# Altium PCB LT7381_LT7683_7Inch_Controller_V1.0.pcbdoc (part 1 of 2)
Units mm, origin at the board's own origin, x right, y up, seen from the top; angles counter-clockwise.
Board outline 88.99 x 77.25 mm, 2 copper layers (Top Layer, Bottom Layer); 119 components, 133 nets, 535 pads, 215 vias.
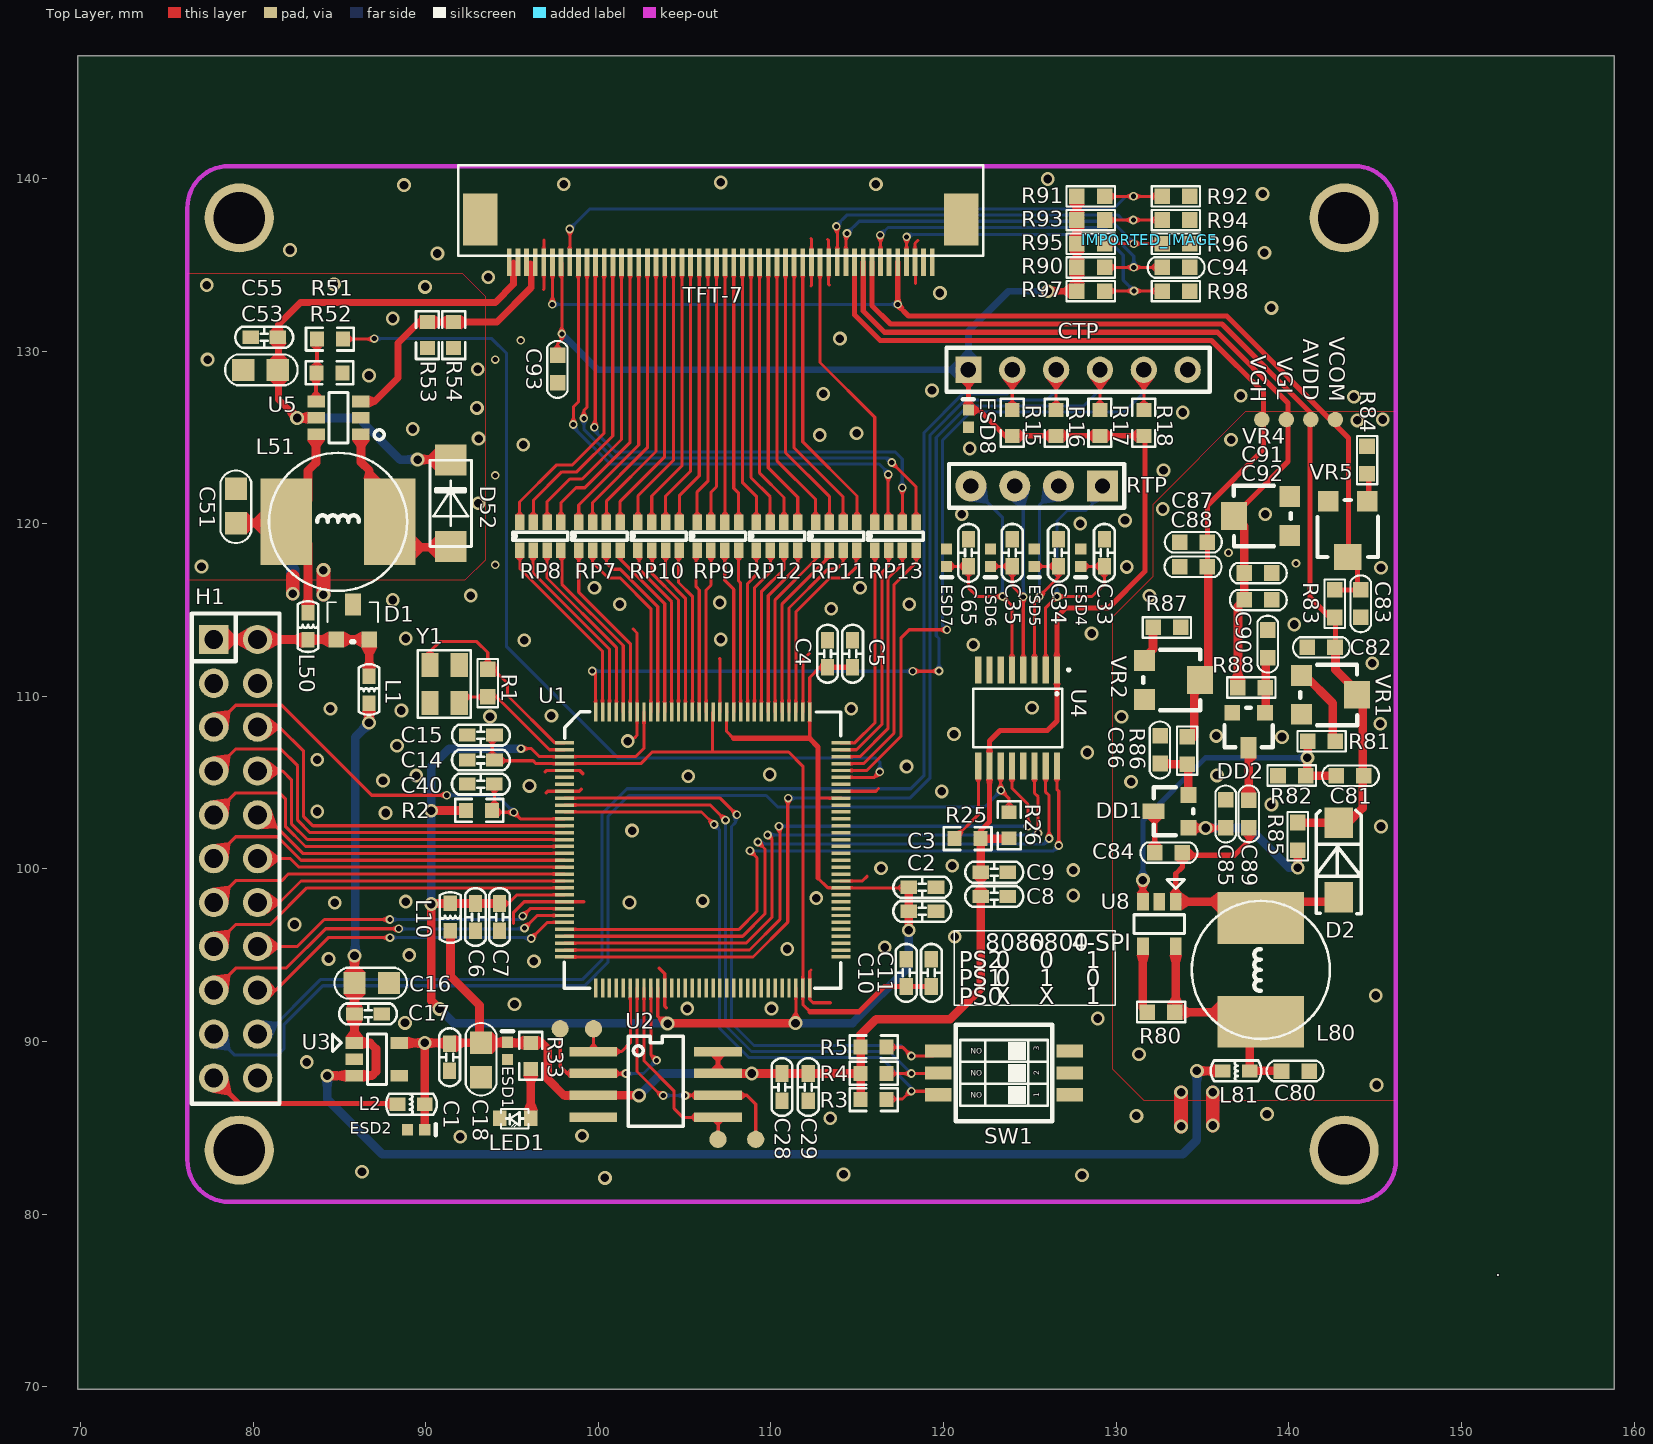
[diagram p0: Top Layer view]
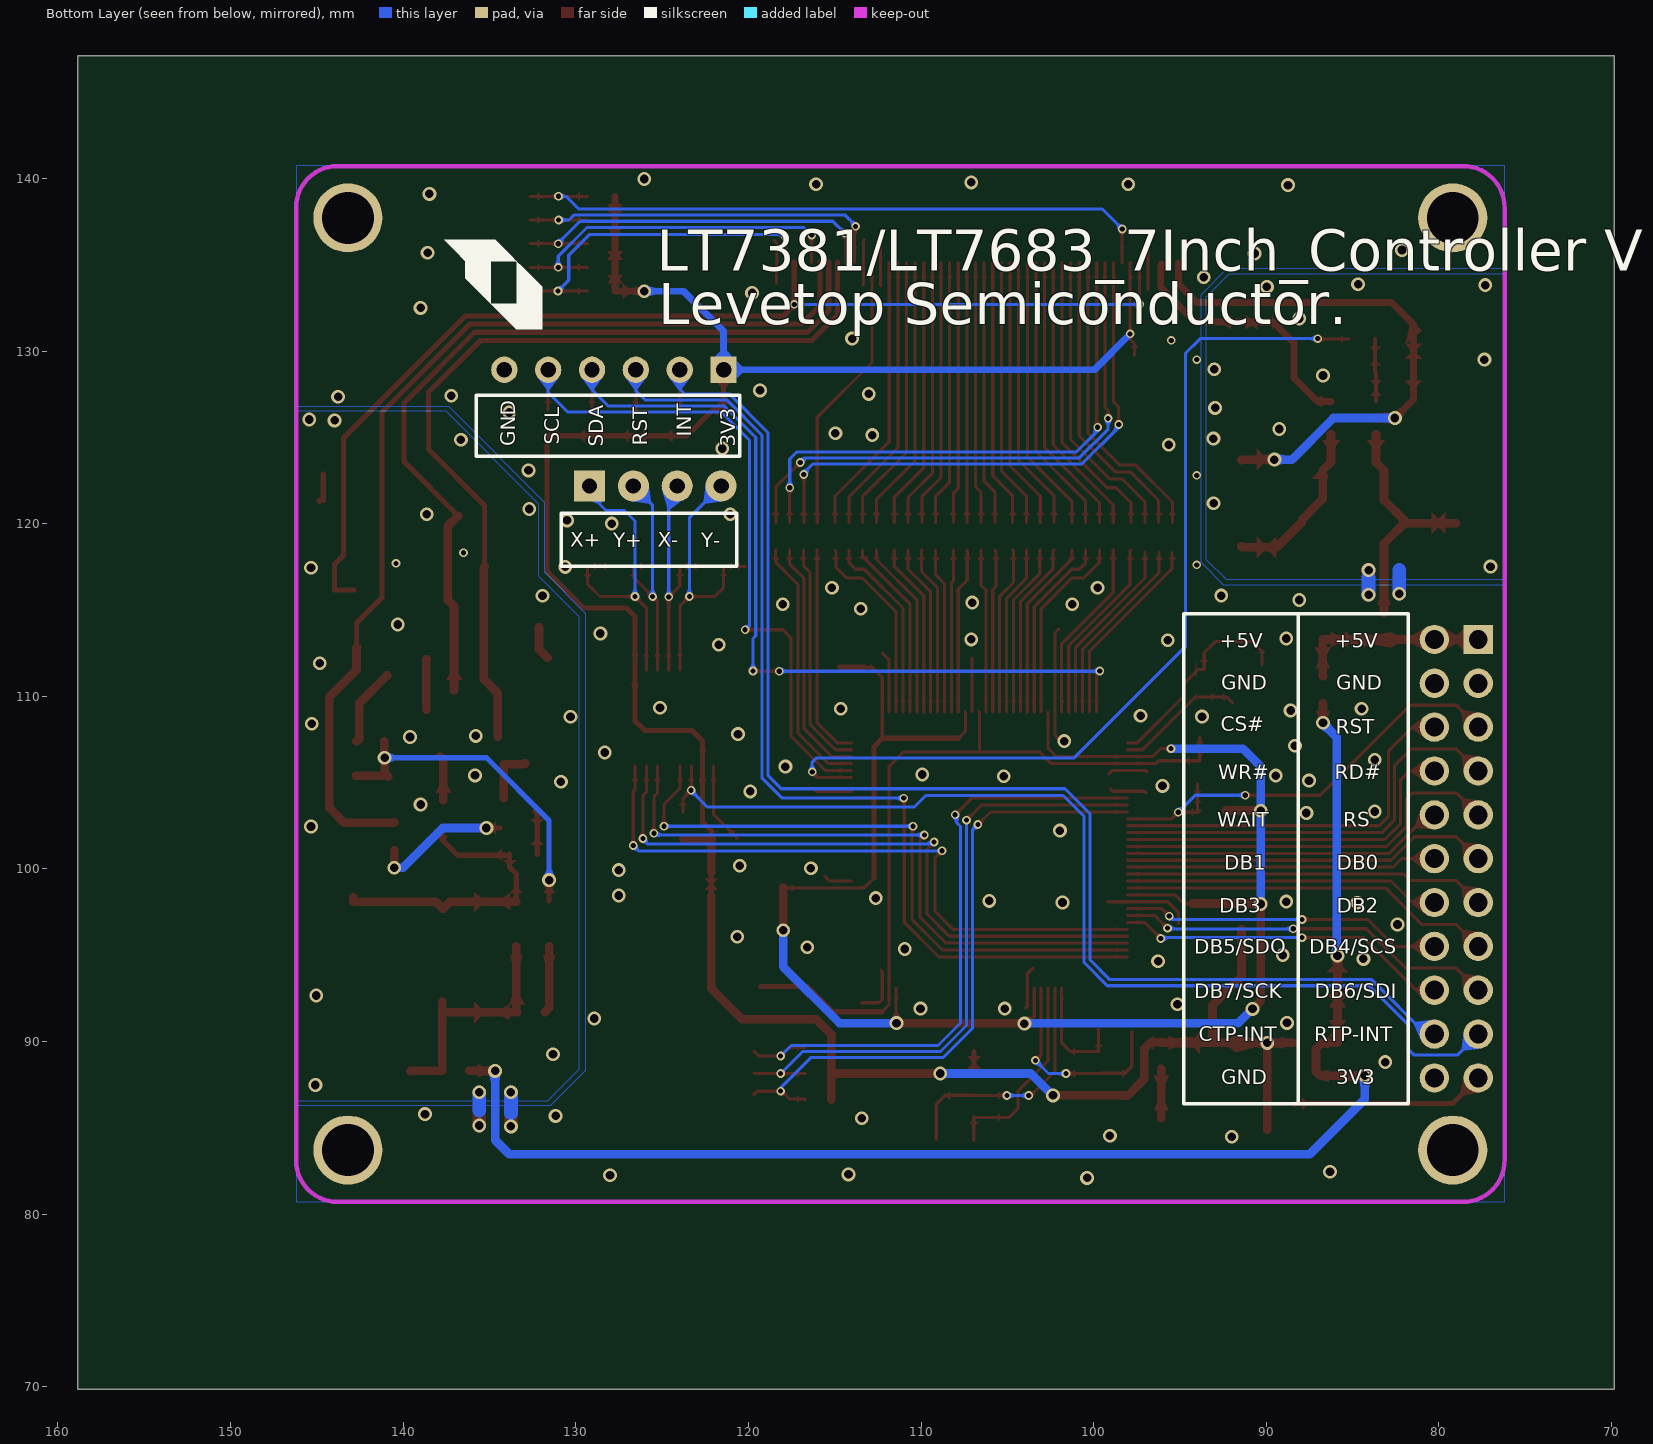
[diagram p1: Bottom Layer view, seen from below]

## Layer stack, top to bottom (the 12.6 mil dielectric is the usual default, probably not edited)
Top Layer: signal copper (thickness not stored)
Dielectric: dielectric 0.32, FR-4, Dk 4.8
Bottom Layer: signal copper (thickness not stored)

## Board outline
158.844,69.85 69.85,69.85 69.85,147.102 158.844,147.102

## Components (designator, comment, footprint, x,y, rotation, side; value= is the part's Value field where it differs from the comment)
C1 "1uF" C0603 91.389,89.878 r270 top
C2 "1uF" C0603 117.983,97.548 r0 top
C3 "0.1uf" C0603 117.983,98.945 r0 top
C4 "1uF" C0603 113.277,111.684 r90 top
C5 "0.1uf" C0603 114.731,111.684 r90 top
C6 "1uF" C0603 92.884,98 r270 top
C7 "0.1uf" C0603 94.281,98 r270 top
C8 "1uF" C0603 122.151,98.413 r0 top
C9 "0.1uf" C0603 122.151,99.81 r0 top
C10 "1uF" C0603 117.834,93.198 r90 top
C11 "0.1uf" C0603 119.288,93.198 r90 top
C14 "1uF" C0603 93.98,106.311 r180 top
C15 "0.1uf" C0603 93.981,107.752 r180 top
C16 "10uF" C0805 85.87,93.397 r0 top
C17 "1uF" C0603 85.878,91.608 r0 top
C18 "10uF" C0805 93.218,89.929 r270 top
C28 "1uF" C0603 110.638,88.15 r270 top
C29 "0.1uf" C0603 112.162,88.15 r270 top
C33 "20pF" C0603 129.314,117.53 r90 top
C34 "20pF" C0603 126.647,117.53 r90 top
C35 "20pF" C0603 123.98,117.53 r90 top
C40 "1uF" C0603 93.978,104.913 r180 top
C51 "22uF/50V" C0805_1 78.994,120.027 r90 top
C53 "22uF/50V" C0805_1 81.433,128.901 r180 top
C55 "0.1uF/50V" C0603 81.432,130.797 r180 top
C65 "20pF" C0603 121.44,117.53 r90 top
C80 "10uF" C0603_1 141.173,88.29 r180 top
C81 "100pF" C0603_1 142.748,105.41 r0 top
C82 "10uF/25V" C0603_1 141.072,112.84 r0 top
C83 "1uF" C0603_1 144.17,116.18 r270 top
C84 "1uF" C0603_1 132.232,100.953 r0 top
C85 "0.1uF" C0603_1 136.347,104.001 r270 top
C86 "0.1uF" C0603_1 132.537,107.709 r270 top
C87 "0.1uF" C0603_1 135.28,118.923 r180 top
C88 "1uF" C0603_1 135.267,117.501 r180 top
C89 "1uF" C0603_1 137.668,102.375 r90 top
C90 "0.1uF" C0603_1 138.786,113.843 r270 top
C91 "0.1uF" C0603_1 137.414,117.145 r0 top
C92 "1uF" C0603_1 137.414,115.583 r0 top
C93 "1uF" C0603_1 97.638,129.756 r270 top
C94 "0.1uF" C0603_1 132.652,134.849 r0 top
CTP "HDR_6P" SIP-6P 121.437,128.917 r0 top
D1 "MMBZ5V6A" SOT-23 84.836,113.296 r0 top
D2 "B340A" SOD-323 142.9,98.349 r0 top
D52 "B340A" DO-214 91.44,121.17 r90 top
DD1 "DAN217U" SOT23 133.198,103.34 r90 top
DD2 "DAN217U_SOT-23" SOT23 137.668,108.065 r180 top
ESD1 "PESD0402MS05" ESD0402 94.742,88.964 r90 top
ESD2 "PESD0402MS05" ESD0402 88.951,84.9 r0 top
ESD4 "PESD0402MS05" ESD0402 127.94,118.528 r270 top
ESD5 "PESD0402MS05" ESD0402 125.25,118.528 r270 top
ESD6 "PESD0402MS05" ESD0402 122.71,118.528 r270 top
ESD7 "PESD0402MS05" ESD0402 120.17,118.528 r270 top
ESD8 "PESD0402MS05" ESD0402 121.437,125.59 r90 top
H1 "CS-1106-2*11B" HDR-TH_22P-P2.54-V-M-R2-C11-S2.54 78.994,100.596 r270 top
IMPORTED_IMAGE "IMPORTED_IMAGE" IMPORTED_IMAGE 131.928,136.443 r0 top
L1 "BEAD 0603 600R&amp;100MHZ" L0603 86.716,110.376 r270 top
L2 "BEAD 0603 600R&amp;100MHZ" L0603 89.154,86.373 r180 top
L10 "BEAD 0603 600R&amp;100MHZ" L0603 91.423,97.215 r90 top
L50 "BEAD 0603 600R&amp;100MHZ" L0603 83.185,114.058 r90 top
L51 "10uH 1A" IND8A 84.916,120.105 r0 top
L80 "10uH/1A" IND8A 138.379,94.146 r90 top
L81 "BEAD 0603 600R&amp;100MHZ" L0603 136.957,88.304 r0 top
LED1 "LED_1" 0603LED 96.085,85.572 r180 top
R1 "1M" R0603_1 93.597,111.565 r270 top
R2 "120R" R0603 93.1,103.39 r180 top
R3 "10K" R0603 115.951,86.645 r180 top
R4 "10K" R0603 115.951,88.164 r180 top
R5 "10K" R0603 115.951,89.693 r180 top
R15 "10K" R0603 123.977,125.844 r90 top
R16 "10K" R0603 126.517,125.836 r90 top
R17 "10K" R0603 129.057,125.844 r90 top
R18 "10K" R0603 131.597,125.844 r90 top
R25 "0R" R0603 121.387,101.761 r0 top
R26 "10K" R0603 123.8,102.532 r90 top
R33 "4.7K" R0603 96.085,89.172 r90 top
R51 "100R" R0603 84.455,130.695 r180 top
R52 "10K" R0603 84.43,128.74 r0 top
R53 "12R" R0603 91.622,130.925 r270 top
R54 "12R" R0603 90.098,130.925 r270 top
R80 "10K" R0603_1 133.401,91.707 r180 top
R81 "100K" R0603_1 142.697,107.391 r180 top
R82 "18K" R0603_1 140.97,105.41 r180 top
R83 "150K" R0603_1 142.646,114.567 r90 top
R84 "100K" R0603_1 144.526,122.885 r90 top
R85 "0R" R0603_1 140.513,101.092 r90 top
R86 "2.2K" R0603_1 134.112,107.658 r270 top
R87 "100K" R0603_1 132.131,113.995 r0 top
R88 "3.3K" R0603_1 138.633,110.503 r180 top
R90 "10K" R0603_1 127.725,134.849 r0 top
R91 "10K" R0603_1 127.725,138.964 r0 top
R92 "NC" R0603_1 132.652,138.964 r0 top
R93 "10K" R0603_1 127.725,137.593 r0 top
R94 "NC" R0603_1 132.652,137.593 r0 top
R95 "NC" R0603_1 127.725,136.221 r0 top
R96 "10K" R0603_1 132.652,136.221 r0 top
R97 "NC" R0603_1 127.725,133.478 r0 top
R98 "10K" R0603_1 132.652,133.478 r0 top
RP7 "22R" 8R4R 100.076,119.265 r90 top
RP8 "22R" 8R4R 96.647,119.265 r90 top
RP9 "22R" 8R4R 106.934,119.265 r90 top
RP10 "22R" 8R4R 103.505,119.265 r90 top
RP11 "22R" 8R4R 113.792,119.265 r90 top
RP12 "22R" 8R4R 110.363,119.265 r90 top
RP13 "22R" 8R4R 117.221,119.265 r90 top
RTP "CON4" SIP-4P 129.203,122.186 r180 top
SW1 "DSHP03TSGET" SW-SMD_6P-L5.4-W5.4-P1.27-LS8.4 123.495,88.189 r90 top
TFT-7 "TFT_50" FPC50-0.5 94.844,135.141 r0 top
U1 "LT768-136" LQFP128L 106.045,101.104 r90 top
U2 "XT25F128B/W25Q128B" SOP-8A 100.457,89.42 r0 top
U3 "HP5013 3-2" SOT23-5 85.879,89.933 r270 top
U4 "TSC2046" TSSOP-16_L5.0-W4.4-P0.65-LS6.4-BL-1 124.289,108.754 r180 top
U5 "HP2302D" SOT23-6 83.646,127.09 r90 top
U8 "HP2301(FP6736)" SOT23-5 133.452,98.108 r180 top
VR1 "50KΩ" RES-ADJ-SMD_G32AT 142.342,110.084 r270 top
VR2 "50KΩ" RES-ADJ-SMD_G32AT 133.248,110.947 r270 top
VR4 "50KΩ" RES-ADJ-SMD_G32AT 138.43,120.447 r90 top
VR5 "50KΩ" RES-ADJ-SMD_G32AT 143.408,119.685 r180 top
Y1 "10M" M3225_1 91.95,109.615 r90 top

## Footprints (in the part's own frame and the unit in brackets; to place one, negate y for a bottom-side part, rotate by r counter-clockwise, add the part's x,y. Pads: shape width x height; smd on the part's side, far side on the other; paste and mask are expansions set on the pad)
8R4R [mm]
  rect 0.9x0.55 smd mask+0.102: 1(-0.79,1.209) 2(-0.79,0.409) 3(-0.79,-0.391) 4(-0.79,-1.191) 5(0.81,-1.191) 6(0.81,-0.391) 7(0.81,0.409) 8(0.81,1.209)
  silkscreen extent -0.22,-1.59 0.24,1.61
0603LED [mm]
  rect 0.8x0.9 smd mask+0.102: 1(0,0) 2(1.8,0)
  silkscreen extent 0.13,-0.53 1.73,0.6
C0603 [mil]
  rect 38x30 smd mask+4: 1(-0.09,-0.02) 2(61.91,-0.02)
  silkscreen extent -35,-24 97,24
C0603_1 [mm]
  rect 0.9x0.9 smd mask+0.102: 1(0,0) 2(1.6,0)
  silkscreen extent -0.83,-0.6 2.47,0.58
C0805 [mm]
  rect 1.3x1.27 smd mask+0.102: 1(0.005,-0.011) 2(2.005,-0.011)
  silkscreen extent -1.15,-0.9 3.05,0.88
C0805_1 [mm]
  rect 1.3x1.27 smd mask+0.102: 1(0.005,-0.011) 2(2.005,-0.011)
  silkscreen extent -1.15,-0.9 3.05,0.88
DO-214 [mm]
  rect 1.8x1.8 smd mask+0.102: 1(-2.488,-0.011) 2(2.512,-0.011)
  silkscreen extent -2.49,-1.21 2.51,1.19
ESD0402 [mm]
  rect 0.65x0.65 smd mask+0.102: 1(1,0) 2(0,0)
  silkscreen extent 1.63,-0.32 1.63,0.33
FPC50-0.5 [mm]
  rect 0.28x1.6 smd mask+0.102: 1(0,0) 2(0.5,0) 3(1,0) 4(1.5,0) 5(2,0) 6(2.5,0) 7(3,0) 8(3.5,0) 9(4,0) 10(4.5,0) 11(5,0) 12(5.5,0) 13(6,0) 14(6.5,0) 15(7,0) 16(7.5,0) 17(8,0) 18(8.5,0) 19(9,0) 20(9.5,0) 21(10,0) 22(10.5,0) 23(11,0) 24(11.5,0) 25(12,0) 26(12.5,0) 27(13,0) 28(13.5,0) 29(14,0) 30(14.5,0) 31(15,0) 32(15.5,0) 33(16,0) 34(16.5,0) 35(17,0) 36(17.5,0) 37(18,0) 38(18.5,0) 39(19,0) 40(19.5,0) 41(20,0) 42(20.5,0) 43(21,0) 44(21.5,0) 45(22,0) 46(22.5,0) 47(23,0) 48(23.5,0) 49(24,0) 50(24.5,0)
  rect 2x3 smd mask+0.102: 51(-1.69,2.475) 52(26.19,2.475)
  silkscreen extent -2.95,0.38 27.45,5.61
HDR-TH_22P-P2.54-V-M-R2-C11-S2.54 [mm]
  rect 1.7x1.7 hole 1.1 paste+0 mask+0.051: 1(-12.7,-1.27)
  round 1.7 hole 1.1 paste+0 mask+0.051: 2(-12.7,1.27) 3(-10.16,-1.27) 4(-10.16,1.27) 5(-7.62,-1.27) 6(-7.62,1.27) 7(-5.08,-1.27) 8(-5.08,1.27) 9(-2.54,-1.27) 10(-2.54,1.27) 11(0,-1.27) 12(0,1.27) 13(2.54,-1.27) 14(2.54,1.27) 15(5.08,-1.27) 16(5.08,1.27) 17(7.62,-1.27) 18(7.62,1.27) 19(10.16,-1.27) 20(10.16,1.27) 21(12.7,-1.27) 22(12.7,1.27)
  silkscreen extent -14.2,-2.54 14.2,2.54
IMPORTED_IMAGE [mm]
IND8A [mm]
  rect 3x5 smd mask+0.102: 1(-2.992,0.003) 2(3.008,0.003)
  silkscreen extent -3.99,-4 4.01,4
L0603 [mil]
  rect 35.43x30 smd mask+4: 1(-31,0) 2(31,0)
  silkscreen extent -59,-24 57,24
LQFP128L [mm]
  rect 0.2x1.1 smd paste+0 mask+0.102: 1(6.2,8) 2(5.8,8) 3(5.4,8) 4(5,8) 5(4.6,8) 6(4.2,8) 7(3.8,8) 8(3.4,8) 9(3,8) 10(2.6,8) 11(2.2,8) 12(1.8,8) 13(1.4,8) 14(1,8) 15(0.6,8) 16(0.2,8) 17(-0.2,8) 18(-0.6,8) 19(-1,8) 20(-1.4,8) 21(-1.8,8) 22(-2.2,8) 23(-2.6,8) 24(-3,8) 25(-3.4,8) 26(-3.8,8) 27(-4.2,8) 28(-4.6,8) 29(-5,8) 30(-5.4,8) 31(-5.8,8) 32(-6.2,8) 65(-6.2,-8) 66(-5.8,-8) 67(-5.4,-8) 68(-5,-8) 69(-4.6,-8) 70(-4.2,-8) 71(-3.8,-8) 72(-3.4,-8) 73(-3,-8) 74(-2.6,-8) 75(-2.2,-8) 76(-1.8,-8) 77(-1.4,-8) 78(-1,-8) 79(-0.6,-8) 80(-0.2,-8) 81(0.2,-8) 82(0.6,-8) 83(1,-8) 84(1.4,-8) 85(1.8,-8) 86(2.2,-8) 87(2.6,-8) 88(3,-8) 89(3.4,-8) 90(3.8,-8) 91(4.2,-8) 92(4.6,-8) 93(5,-8) 94(5.4,-8) 95(5.8,-8) 96(6.2,-8)
  rect 1.1x0.2 smd paste+0 mask+0.102: 33(-8,6.2) 34(-8,5.8) 35(-8,5.4) 36(-8,5) 37(-8,4.6) 38(-8,4.2) 39(-8,3.8) 40(-8,3.4) 41(-8,3) 42(-8,2.6) 43(-8,2.2) 44(-8,1.8) 45(-8,1.4) 46(-8,1) 47(-8,0.6) 48(-8,0.2) 49(-8,-0.2) 50(-8,-0.6) 51(-8,-1) 52(-8,-1.4) 53(-8,-1.8) 54(-8,-2.2) 55(-8,-2.6) 56(-8,-3) 57(-8,-3.4) 58(-8,-3.8) 59(-8,-4.2) 60(-8,-4.6) 61(-8,-5) 62(-8,-5.4) 63(-8,-5.8) 64(-8,-6.2) 97(8,-6.2) 98(8,-5.8) 99(8,-5.4) 100(8,-5) 101(8,-4.6) 102(8,-4.2) 103(8,-3.8) 104(8,-3.4) 105(8,-3) 106(8,-2.6) 107(8,-2.2) 108(8,-1.8) 109(8,-1.4) 110(8,-1) 111(8,-0.6) 112(8,-0.2) 113(8,0.2) 114(8,0.6) 115(8,1) 116(8,1.4) 117(8,1.8) 118(8,2.2) 119(8,2.6) 120(8,3) 121(8,3.4) 122(8,3.8) 123(8,4.2) 124(8,4.6) 125(8,5) 126(8,5.4) 127(8,5.8) 128(8,6.2)
  silkscreen extent -8,-8.01 8,8.01
M3225_1 [mm]
  rect 1.4x1 smd mask+0.102: 1(0,0) 2(2.2,0) 3(2.2,1.7) 4(0,1.7)
  silkscreen extent -0.85,-0.65 3.05,2.4
R0603 [mm]
  rect 0.806x0.864 smd paste-100 mask+0.051: 1(-0.753,0) 2(0.753,0)
  silkscreen extent -1.39,-0.66 1.39,0.66
R0603_1 [mm]
  rect 0.9x0.9 smd mask+0.102: 1(0,0) 2(1.6,0)
  silkscreen extent -0.6,-0.6 2.2,0.58
RES-ADJ-SMD_G32AT [mil]
  rect 47.2x47.2 smd paste+0 mask+2: 1(44.3,-63.5) 3(-44.3,-63.5)
  rect 63x59.1 smd paste+0 mask+2: 2(0,63.5)
  silkscreen extent -69,-66 69,64
SIP-4P [mm]
  rect 1.8x1.8 hole 0.889 mask+0.102: 1(0,0)
  round 1.8 hole 0.889 mask+0.102: 2(2.54,0) 3(5.08,0) 4(7.62,0)
  silkscreen extent -1.27,-1.27 8.89,1.27
SIP-6P [mil]
  rect 60x60 hole 35 mask+4: 1(0,0)
  round 60 hole 35 mask+4: 2(100,0) 3(200,0) 4(300,0) 5(400,0) 6(500,0)
  silkscreen extent -50,-50 550,50
SOD-323 [mil]
  rect 65x70 smd mask+4: 1(-0.42,0.31) 2(-0.42,170.31)
  silkscreen extent -51,-37 51,199
SOP-8A [mm]
  rect 2.778x0.55 smd mask+0.102: 1(-0.75,0.005) 2(-0.75,-1.265) 3(-0.75,-2.535) 4(-0.75,-3.805) 5(6.473,-3.805) 6(6.473,-2.535) 7(6.473,-1.265) 8(6.473,0.005)
  silkscreen extent 1.27,-4.31 4.45,0.89
SOT23 [mil]
  rect 36x36 smd paste+0 mask+4: 1(-37.5,-39) 2(37.5,-39)
  rect 36x50 smd paste+0 mask+4: 3(0,41)
  silkscreen extent -55,-50 55,40
SOT23-5 [mil]
  rect 27x40 smd mask+4: 1(0.28,-0.14) 2(37.68,-0.14) 3(75.08,-0.14) 4(75.08,102.22) 5(0.28,102.22)
  silkscreen extent -20,-50 95,73
SOT23-6 [mil]
  rect 27x40 smd mask+4: 1(-75.07,-102.5) 2(-37.67,-102.5) 3(-0.27,-102.5) 4(-0.27,-0.14) 5(-37.67,-0.14) 6(-75.07,-0.14)
  silkscreen extent -95,-155 20,-30
SOT-23 [mil]
  rect 36x36 smd mask+4: 1(-0.41,-0.04) 2(74.59,-0.04)
  rect 36x50 smd mask+4: 3(37.59,79.96)
  silkscreen extent -20,-5 95,85
SW-SMD_6P-L5.4-W5.4-P1.27-LS8.4 [mil]
  rect 30x60 smd paste+0 mask+2: 1(-50,-150) 2(0,-150) 3(50,-150) 4(50,150) 5(0,150) 6(-50,150)
  silkscreen extent -110,-110 110,110
TSSOP-16_L5.0-W4.4-P0.65-LS6.4-BL-1 [mm]
  rect 0.364x1.56 smd paste+0 mask+0.051: 1(-2.275,-2.78) 2(-1.625,-2.78) 3(-0.975,-2.78) 4(-0.325,-2.78) 5(0.325,-2.78) 6(0.975,-2.78) 7(1.625,-2.78) 8(2.275,-2.78) 9(2.275,2.78) 10(1.625,2.78) 11(0.975,2.78) 12(0.325,2.78) 13(-0.325,2.78) 14(-0.975,2.78) 15(-1.625,2.78) 16(-2.275,2.78)
  silkscreen extent -3.03,-2.85 2.58,1.7

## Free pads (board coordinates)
  round 4 hole 3 mask+0.102: 1(79.2,83.716) 2(143.2,83.716) 3(143.2,137.716) 4(79.2,137.716)
  round 1 smd mask+0.102: TP4(109.118,84.341) TP5(106.934,84.341) TP6(99.72,90.742) TP7(97.79,90.742)
  round 0.9 smd mask+0.102: TP7(142.697,126.035) TP8(141.275,126.035) TP10(139.852,126.035) TP11(138.43,126.035)

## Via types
v1: diameter 0.8, hole 0.5, Top Layer to Bottom Layer, 151 vias
v2: diameter 0.5, hole 0.3, Top Layer to Bottom Layer, 64 vias

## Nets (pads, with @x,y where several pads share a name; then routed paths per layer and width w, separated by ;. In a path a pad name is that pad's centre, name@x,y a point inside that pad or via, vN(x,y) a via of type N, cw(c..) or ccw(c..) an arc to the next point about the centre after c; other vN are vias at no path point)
$1N16243: R51.2 R52.1 U5.4 | length 3.6
  Top Layer w0.254: U5.4@83.65,127.083 83.65,128.756 83.702,128.807 R51.2@83.702,130.695
$1N16244: C51.1 L50.2 L51.1 U5.6 | length 14.5
  Top Layer w0.5: C51.1@79.005,120.032 81.848,120.032 L51.1@81.924,120.108 ; L50.2@83.185,114.845 83.185,118.847 L51.1@81.924,120.108 ; U5.6@83.65,125.183 83.65,123.54 83.185,123.075 83.185,121.369 L51.1@81.924,120.108
$1N16251: D52.1 L51.2 U5.1 | length 9.9
  Top Layer w0.5: U5.1@86.25,125.183 86.25,123.566 86.741,123.075 86.741,121.424 87.924,120.241 L51.2@87.924,120.108 89.402,118.63 91.399,118.63 D52.1@91.451,118.682
$1N48183: U4.13
$1N48192: R25.1 U4.9 | length 4.8
  Top Layer w0.18: R25.1@120.633,101.761 122.014,103.141 U4.9@122.014,105.974
$1N53057: LED1.1 R33.1 | length 2.8
  Top Layer w0.5: LED1.1@96.085,85.572 R33.1@96.085,88.419
$1N79041: C90.2 DD2.1 R88.1 | length 2.9
  Top Layer w0.5: C90.2@138.633,112.154 138.651,112.136 DD2.1@138.651,109.228
$1N79043: C85.2 DD1.1 R85.1 | length 8.8
  Top Layer w0.3: DD1.1@134.391,102.388 134.404,102.375 v1(135.179,102.375) 135.864,102.375 135.89,102.401
  Top Layer w0.5: v1(140.513,100.076) R85.1@140.513,101.092
  Bottom Layer w0.5: v1(135.179,102.375) 137.706,102.375 140.005,100.076 v1(140.513,100.076)
$1N79044: C86.2 DD1.2 R86.2 | length 3.2
  Top Layer w0.5: C86.2@132.944,106.109 132.994,106.058 134.163,106.058 DD1.2@134.163,104.115
$1N79046: C84.2 C89.1 D2.1 L80.2 U8.1 | length 18
  Top Layer w0.3: U8.1@133.445,98.112 133.445,99.727 133.832,100.114 133.832,100.851 133.883,100.8 136.855,100.8 137.719,101.664 137.719,102.375 C89.1@137.668,102.375
  Top Layer w0.5: U8.1@133.445,98.112 137.27,98.112 137.689,97.693 138.104,98.108 142.863,98.108 142.89,98.135 D2.1@142.89,98.357
$1N79048: C81.1 R81.2 R82.1 U8.3 | length 19.6
  Top Layer w0.3: U8.3@131.545,98.162 v1(131.545,99.355)
  Top Layer w0.5: R82.1@140.868,105.359 141.072,105.562 v1(141.072,106.439) 141.097,106.465 R81.2@141.097,107.391 ; R82.1@140.97,105.41 C81.1@142.748,105.41
  Bottom Layer w0.3: v1(131.545,99.355) 131.545,102.805 135.179,106.439 v1(141.072,106.439)
$1N79058: C80.2 L80.1 L81.2 R80.1 U8.5 | length 14
  Top Layer w0.3: R80.1@133.401,91.707 R80.1@133.445,91.751
  Top Layer w0.5: R80.1@133.401,91.707 133.415,91.693 137.689,91.693 L80.1@137.744,91.637 ; R80.1@133.445,91.751 U8.5@133.445,95.512 ; L80.1@137.744,92.298 L80.1@137.744,91.637 ; C80.2@139.573,88.29 139.56,88.304 L81.2@137.744,88.304 L80.1@137.744,91.637
$1N83513: C89.2 DD2.3 | length 2.6
  Top Layer w0.5: C89.2@137.668,103.975 137.668,106.312 DD2.3@137.871,106.515
$1N83514: C84.1 DD1.3 | length 2.5
  Top Layer w0.3: C84.1@132.232,100.851 132.232,103.213 DD1.3@132.359,103.34
$1N95806: R81.1 VR1.3 | length 4.5
  Top Layer w0.5: VR1.3@140.932,111.209 142.545,109.596 142.545,107.544 R81.1@142.697,107.391
$1N101796: R84.1 VR5.3 | length 1.6
  Top Layer w0.3: VR5.3@144.628,121.341 R84.1@144.628,122.885 ; VR5.3@144.838,121.298 VR5.3@144.882,121.341
$1N109903: R87.1 VR2.3 | length 2
  Top Layer w0.5: VR2.3@131.636,112.23 132.131,112.725 R87.1@132.131,113.995
+5V: C16.1 C17.1 L1.2 L81.1 U3.1 U3.3 | length 84.5
  Top Layer w0.5: v1(84.301,88.026) U3.3@85.875,88.026 86.879,88.026 87.125,88.272 87.125,89.572 86.771,89.926 U3.1@85.875,89.926 C17.1@85.875,91.607 C16.1@85.875,93.386 v1(85.875,94.972) ; v1(86.716,108.471) L1.2@86.716,109.589 ; v1(134.671,88.304) L81.1@136.169,88.304
  Bottom Layer w0.5: v1(84.301,88.026) 84.301,86.654 87.478,83.478 133.858,83.478 134.671,84.29 v1(134.671,88.304) ; v1(85.875,94.972) 85.925,95.022 85.925,107.63 86.716,108.42 v1(86.716,108.471)
B0: RP11.5 TFT-7.35 | length 16.4
  Top Layer w0.18: TFT-7.35@111.844,135.141 111.844,124.745 114.983,121.606 RP11.5@114.983,120.075
B1: RP11.6 TFT-7.34 | length 16.2
  Top Layer w0.18: TFT-7.34@111.344,135.141 111.344,124.382 114.183,121.542 RP11.6@114.183,120.075
B2: RP11.7 TFT-7.33 | length 16.1
  Top Layer w0.18: TFT-7.33@110.844,135.141 110.844,124.12 113.383,121.58 RP11.7@113.383,120.075
B3: RP11.8 TFT-7.32 | length 16
  Top Layer w0.18: TFT-7.32@110.344,135.141 110.344,123.654 112.583,121.415 RP11.8@112.583,120.075
B4: RP12.5 TFT-7.31 | length 15.8
  Top Layer w0.18: TFT-7.31@109.844,135.141 109.844,123.24 111.554,121.53 RP12.5@111.554,120.075
B5: RP12.6 TFT-7.30 | length 15.7
  Top Layer w0.18: TFT-7.30@109.344,135.141 109.344,122.927 110.754,121.517 RP12.6@110.754,120.075
B6: RP12.7 TFT-7.29 | length 15.5
  Top Layer w0.18: TFT-7.29@108.844,135.141 108.844,122.665 109.954,121.555 RP12.7@109.954,120.075
B7: RP12.8 TFT-7.28 | length 15.4
  Top Layer w0.18: TFT-7.28@108.344,135.141 108.344,122.403 109.154,121.593 RP12.8@109.154,120.075
CTP_INT: CTP.2 H1.20 R15.2 | length 79.2
  Top Layer w0.18: R15.2@123.977,126.597 CTP.2@123.977,128.917
  Bottom Layer w0.18: H1.20@80.264,90.436 80.747,90.436 83.897,93.587 99.06,93.587 100.203,94.73 100.203,103.187 101.664,104.648 118.097,104.648 118.872,105.423 118.872,125.286 121.107,127.521 123.698,127.521 123.977,127.801 CTP.2@123.977,128.917
CTP_RST: CTP.3 R16.2 U1.32 | length 61.4
  Top Layer w0.18: U1.32@98.045,94.904 108.957,94.904 110.975,96.922 110.975,104.079 v2(110.998,104.102) ; R16.2@126.517,126.589 CTP.3@126.517,128.917
  Bottom Layer w0.18: v2(110.998,104.102) 118.046,104.102 119.222,105.278 119.222,125.14 121.252,127.171 125.989,127.171 126.517,127.699 CTP.3@126.517,128.917
CTP_SCL: CTP.5 R18.2 U1.92 | length 40.4
  Top Layer w0.18: U1.92@114.045,105.704 115.557,105.704 117.525,107.672 117.525,113.373 118.008,113.856 v2(120.193,113.856) ; R18.2@131.597,126.597 CTP.5@131.597,128.917
  Bottom Layer w0.18: v2(120.193,113.856) 119.939,114.11 119.939,124.829 121.58,126.47 130.47,126.47 131.597,127.597 CTP.5@131.597,128.917
CTP_SDA: CTP.4 R17.2 U1.128 | length 50.3
  Top Layer w0.18: v2(99.644,111.467) 99.845,111.266 U1.128@99.845,109.104 ; v2(118.212,111.455) 119.722,111.455 v2(119.736,111.468) ; R17.2@129.057,126.597 CTP.4@129.057,128.917
  Bottom Layer w0.18: v2(99.644,111.467) 99.656,111.455 v2(118.212,111.455) ; v2(119.736,111.468) 119.736,113.348 119.573,113.511 119.573,124.995 121.398,126.82 128.128,126.82 129.057,127.75 CTP.4@129.057,128.917
DE: RP13.7 TFT-7.9 | length 31.9
  Top Layer w0.18: v2(98.552,125.743) 98.552,126.759 98.844,127.051 TFT-7.9@98.844,135.141 ; v2(116.789,122.848) 116.789,120.097 RP13.7@116.812,120.075
  Bottom Layer w0.18: v2(98.552,125.743) 98.552,125.594 100.683,123.462 116.263,123.462 116.789,122.936 v2(116.789,122.848)
DITH: R97.2 R98.1 TFT-7.47 | length 20.2
  Top Layer w0.18: TFT-7.47@117.844,135.141 117.856,135.154 v2(117.856,136.614) ; R97.2@129.325,133.478 v2(131.032,133.478) R98.1@132.652,133.478
  Bottom Layer w0.18: v2@117.856,136.716 117.958,136.716 118.001,136.759 129.193,136.759 130.404,135.548 130.404,134.106 v2(131.032,133.478)
FLASH_SPI_CS0: U1.37
FLASH_SPI_CS1: pad.TP6 U1.38 U2.1 | length 6.9
  Top Layer w0.18: pad.TP6@99.72,90.742 99.72,89.438 U2.1@99.707,89.425 101.351,89.425 101.854,89.928 101.854,93.095 U1.38@101.845,93.104
FLASH_SPI_SCLK: pad.TP4 U1.39 U2.6 | length 14.5
  Top Layer w0.18: U1.39@102.245,93.104 102.245,88.267 103.632,86.88 v2(103.759,86.88) ; v2(105.029,86.88) 105.034,86.885 U2.6@106.93,86.885
  Top Layer w0.2: U2.6@106.93,86.885 108.607,86.885 109.118,86.373 pad.TP4@109.118,84.341
  Bottom Layer w0.18: v2(103.759,86.88) v2(105.029,86.88)
FLASH_SPI_SI: pad.TP5 U1.40 U2.5 | length 11.8
  Top Layer w0.18: U1.40@102.645,93.104 102.645,88.883 104.394,87.134 104.394,86.118 104.897,85.615 U2.5@106.93,85.615
  Top Layer w0.2: U2.5@106.93,85.615 106.934,85.611 pad.TP5@106.934,84.29
FLASH_SPI_SO: pad.TP7@97.79,90.742 U1.41 U2.2 | length 12.4
  Top Layer w0.18: U2.2@99.707,88.155 99.712,88.15 v2(101.6,88.15) ; U1.41@103.045,93.104 103.045,89.245 v2(103.378,88.912)
  Top Layer w0.2: pad.TP7@97.79,90.539 97.79,88.558 98.193,88.155 U2.2@99.707,88.155
  Bottom Layer w0.18: v2(101.6,88.15) 102.616,88.15 v2(103.378,88.912)
G0: RP9.5 TFT-7.27 | length 15.2
  Top Layer w0.18: TFT-7.27@107.844,135.141 107.844,122.053 108.125,121.772 RP9.5@108.125,120.075
G1: RP9.6 TFT-7.26 | length 15.1
  Top Layer w0.18: RP9.6@107.325,120.075 107.34,120.09 107.34,121.265 107.344,121.268 TFT-7.26@107.344,135.141
G2: RP9.7 TFT-7.25 | length 15.2
  Top Layer w0.18: RP9.7@106.525,120.075 106.528,120.077 106.528,121.832 106.844,122.148 TFT-7.25@106.844,135.141
G3: RP9.8 TFT-7.24 | length 15.3
  Top Layer w0.18: RP9.8@105.725,120.075 105.725,121.842 106.344,122.46 TFT-7.24@106.344,135.141
G4: RP10.5 TFT-7.23 | length 15.5
  Top Layer w0.18: RP10.5@104.696,120.075 104.696,121.625 105.844,122.773 TFT-7.23@105.844,135.141
G5: RP10.6 TFT-7.22 | length 15.7
  Top Layer w0.18: RP10.6@103.896,120.075 103.896,121.587 105.344,123.035 TFT-7.22@105.344,135.141
G6: RP10.7 TFT-7.21 | length 15.8
  Top Layer w0.18: RP10.7@103.096,120.075 103.096,121.6 104.844,123.348 TFT-7.21@104.844,135.141
G7: RP10.8 TFT-7.20 | length 15.9
  Top Layer w0.18: RP10.8@102.296,120.075 102.296,121.613 104.344,123.661 TFT-7.20@104.344,135.141
GND: C1.2 C2.2 C3.2 C4.2 C5.2 C6.2 C7.2 C8.2 C9.2 C10.2 C11.2 C14.2 C15.2 C16.2 C17.2 C18.2 C28.2 C29.2 C33.2 C34.2 C35.2 C40.2 C51.2 C53.2 C55.2 C65.2 C80.1 C82.1 C83.2 C85.1 C86.1 C87.2 C88.2 C90.1 C91.2 C92.2 C93.2 C94.2 CTP.6 D1.3 DD2.2 ESD1.2 ESD2.2 ESD4.2 ESD5.2 ESD6.2 ESD7.2 ESD8.2 H1.3 H1.4 H1.22 LED1.2 pad.1 pad.2 pad.3 pad.4 R52.2 R53.2 R54.2 R82.2 R84.2 R87.2 R92.2 R94.2 R96.2 R98.2 SW1.1 SW1.2 SW1.3 TFT-7.5 TFT-7.36 TFT-7.38 TFT-7.48 TFT-7.51 TFT-7.52 U1.5 U1.6 U1.7 U1.8 U1.24 U1.43 U1.64 U1.76 U1.89 U1.98 U1.110 U1.122 U2.4 U3.2 U4.6 U5.2 U8.2 VR4.3 Y1.2 Y1.4 | length 53.7
  Top Layer w0.18: 95.098,96.838 95.098,97.498 95.703,98.104 U1.24@98.045,98.104 99.158,98.104 99.162,98.108 ; 96.825,133.566 96.844,133.585 TFT-7.5@96.844,135.141 96.844,136.443 ; 102.006,113.907 102.245,113.668 U1.122@102.245,109.104 102.245,107.745 102.108,107.608 ; 103.53,94.247 103.845,93.933 U1.43@103.845,93.104 103.845,92.053 103.937,91.961 ; 107.036,112.18 107.045,112.17 U1.110@107.045,109.104 ; U1.98@111.845,109.104 111.845,112.112 112.217,112.484 ; 112.319,94.146 112.245,94.072 U1.64@112.245,93.104 112.245,92.441 112.434,92.253 113.45,92.253 ; 112.319,133.77 112.344,133.794 TFT-7.36@112.344,135.141 112.344,136.488 112.319,136.513 ; 113.284,136.462 113.344,136.402 TFT-7.38@113.344,135.141 113.344,133.862 113.386,133.82 ; U1.76@114.045,99.304 115.293,99.304 115.57,99.581 ; U1.89@114.045,104.504 116.073,104.504 116.23,104.661 ; 118.364,133.922 118.364,135.121 TFT-7.48@118.344,135.141 118.344,136.238 118.516,136.411
  Top Layer w0.2: 96.926,105.626 97.004,105.704 U1.5@98.045,105.704 98.932,105.704 99.111,105.525 ; 96.977,104.407 97.074,104.504 U1.8@98.045,104.504 98.903,104.504 99.009,104.61
  Top Layer w0.8: v1(82.296,115.939) 82.296,116.955 ; v1(84.074,115.888) v1(84.074,117.31) ; v1(133.756,85.09) v1(133.756,87.071) ; v1(135.585,85.141) v1(135.585,87.071)
  Bottom Layer w0.8: v1(82.296,115.939) 82.296,117.31 ; v1(84.074,115.888) 84.074,116.853 ; 133.756,85.852 v1(133.756,87.071) ; 135.585,86.004 v1(135.585,87.071)
  other v1: 100.381,82.106 128.016,82.258 114.198,82.309 86.309,82.462 91.999,84.494 99.06,84.544 113.436,85.56 131.166,85.7 138.735,85.801 145.085,87.491 83.109,88.812 131.318,89.269 88.798,91.084 128.93,91.338 105.156,91.91 110.033,91.91 95.148,92.164 145.034,92.672 96.266,94.654 84.379,94.793 89.052,95.009 110.947,95.365 116.586,95.466 120.65,96.076 82.398,96.787 84.734,98.044 101.803,98.057 88.849,98.108 106.045,98.152 112.624,98.311 127.508,98.464 127.508,99.937 116.383,100.038 120.498,100.191 101.956,102.223 145.339,102.464 87.681,103.239 83.718,103.327 138.989,103.734 119.888,104.496 96.012,104.814 130.861,105.054 87.528,105.118 105.207,105.372 89.459,105.41 135.839,105.423 109.931,105.474 117.856,105.931 83.718,106.324 128.321,106.744 88.341,107.137 101.702,107.404 139.598,107.645 135.788,107.709 120.599,107.811 145.288,108.407 130.302,108.814 93.726,108.827 97.282,108.878 88.595,109.182 84.48,109.284 114.656,109.284 125.12,109.335 144.831,111.912 121.717,112.992 95.707,113.246 107.086,113.297 88.849,113.348 128.575,113.64 140.31,114.161 113.487,115.075 101.244,115.329 118.008,115.329 107.036,115.431 88.087,115.583 131.928,115.824 92.608,115.837 99.771,116.294 115.164,116.294 145.339,117.45 130.607,117.5 77.013,117.514 127.914,120.003 130.505,120.193 121.056,120.548 138.633,120.548 132.69,120.853 93.051,121.182 132.74,123.088 121.514,124.358 95.656,124.575 136.652,124.866 93.066,124.93 112.827,125.134 114.96,125.235 89.256,125.489 143.967,125.984 145.44,126.035 133.858,126.441 92.964,126.708 143.764,127.356 137.211,127.406 113.03,127.521 119.329,127.724 86.716,128.588 93.015,128.944 77.368,129.502 113.995,130.722 88.087,131.89 138.989,132.5 119.786,133.363 89.967,133.719 77.318,133.82 84.684,133.871 93.624,134.278 90.678,135.649 138.582,135.7 82.144,135.852 138.481,139.104 88.748,139.612 97.993,139.662 116.078,139.662 107.094,139.771 126.035,139.967
  other v2: 94.031,117.615 140.411,117.704 136.5,118.313 94.031,122.797 94.031,129.502 95.504,130.62
HSYNC: RP13.6 TFT-7.11 | length 32.1
  Top Layer w0.18: v2(99.771,125.591) 99.822,125.642 99.822,135.12 TFT-7.11@99.844,135.141 ; v2(117.602,122.086) 117.602,122.127 117.612,122.137 RP13.6@117.612,120.075
  Bottom Layer w0.18: v2(99.771,125.591) 99.771,125.388 100.995,124.163 117.187,124.163 117.602,123.749 v2(117.602,122.086)
L/R: R93.2 R94.1 TFT-7.39 | length 23
  Top Layer w0.18: v2(113.792,137.224) 113.844,137.172 TFT-7.39@113.844,135.141 ; R93.2@129.325,137.593 v2(130.994,137.593) R94.1@132.652,137.593
  Bottom Layer w0.18: v2(113.792,137.224) 113.792,137.275 114.388,137.871 130.112,137.871 130.391,137.593 v2(130.994,137.593)
LCD_AVDD: C81.2 C82.2 D2.2 pad.TP8 R83.1 R85.2 TFT-7.43 VR1.2 | length 58.6
  Top Layer w0.3: TFT-7.43@115.844,135.141 115.844,132.632 116.916,131.56 136.123,131.56 141.224,126.459 141.224,125.933 141.224,115.722 142.697,114.249 C82.2@142.697,113.018
  Top Layer w0.5: R85.2@140.513,102.692 140.53,102.675 D2.2@142.89,102.675 143.416,102.675 144.272,103.53 144.272,109.969 142.697,111.544 142.697,112.814 C82.2@142.672,112.84
LCD_B0: RP11.4 U1.99 | length 11.4
  Top Layer w0.18: U1.99@111.445,109.104 111.445,114.886 113.411,116.852 114.3,116.852 114.935,117.487 114.935,118.427 RP11.4@114.983,118.475
LCD_B1: RP11.3 U1.100 | length 11
  Top Layer w0.18: U1.100@111.045,109.104 111.045,115.121 113.284,117.36 113.792,117.36 114.183,117.751 RP11.3@114.183,118.475
LCD_B2: RP11.2 U1.101 | length 10.5
  Top Layer w0.18: U1.101@110.645,109.104 110.645,115.356 113.383,118.094 RP11.2@113.383,118.475
LCD_B3: RP11.1 U1.102 | length 10.3
  Top Layer w0.18: U1.102@110.245,109.104 110.245,115.591 112.583,117.929 RP11.1@112.583,118.475
LCD_B4: RP12.4 U1.103 | length 10.1
  Top Layer w0.18: U1.103@109.845,109.104 109.845,115.826 111.554,117.535 RP12.4@111.554,118.475
LCD_B5: RP12.3 U1.104 | length 9.9
  Top Layer w0.18: U1.104@109.445,109.104 109.445,116.061 110.754,117.37 RP12.3@110.754,118.475
LCD_B6: RP12.2 U1.105 | length 9.8
  Top Layer w0.18: U1.105@109.045,109.104 109.045,116.296 109.982,117.233 109.982,118.446 RP12.2@109.954,118.475
LCD_B7: RP12.1 U1.106 | length 9.6
  Top Layer w0.18: U1.106@108.645,109.104 108.645,116.531 109.154,117.04 RP12.1@109.154,118.475
LCD_DE: RP13.2 U1.95 | length 13.3
  Top Layer w0.18: U1.95@114.045,106.904 114.957,106.904 116.424,108.371 116.424,117.171 116.812,117.559 RP13.2@116.812,118.475
LCD_G0: RP9.4 U1.107 | length 9.4
  Top Layer w0.18: RP9.4@108.125,118.475 108.125,116.677 108.245,116.557 U1.107@108.245,109.104
LCD_G1: RP9.3 U1.108 | length 9.6
  Top Layer w0.18: RP9.3@107.325,118.475 107.325,116.715 107.845,116.195 U1.108@107.845,109.104
LCD_G2: RP9.2 U1.112 | length 9.5
  Top Layer w0.18: U1.112@106.245,109.104 106.245,116.163 106.525,116.443 RP9.2@106.525,118.475
LCD_G3: RP9.1 U1.113 | length 9.5
  Top Layer w0.18: RP9.1@105.725,118.475 105.664,118.414 105.664,116.344 105.845,116.163 U1.113@105.845,109.104
LCD_G4: RP10.4 U1.114 | length 9.7
  Top Layer w0.18: RP10.4@104.696,118.475 104.648,118.427 104.648,116.598 105.445,115.801 U1.114@105.445,109.104
LCD_G5: RP10.3 U1.115 | length 9.8
  Top Layer w0.18: RP10.3@103.896,118.475 103.896,116.84 105.045,115.691 U1.115@105.045,109.104
LCD_G6: RP10.2 U1.116 | length 10
  Top Layer w0.18: RP10.2@103.096,118.475 103.124,118.446 103.124,117.102 104.645,115.581 U1.116@104.645,109.104
LCD_G7: RP10.1 U1.117 | length 10.2
  Top Layer w0.18: RP10.1@102.296,118.475 102.362,118.408 102.362,117.354 104.245,115.471 U1.117@104.245,109.104
LCD_HSYNC: RP13.3 U1.94 | length 14.1
  Top Layer w0.18: U1.94@114.045,106.504 115.157,106.504 116.775,108.121 116.775,116.821 117.612,117.659 RP13.3@117.612,118.475
LCD_PCLK: RP13.1 U1.96 | length 12.5
  Top Layer w0.18: U1.96@114.045,107.304 114.857,107.304 116.025,108.472 116.025,118.461 RP13.1@116.012,118.475
LCD_R0: RP7.4 U1.118 | length 10.4
  Top Layer w0.18: RP7.4@101.267,118.475 101.267,117.939 103.845,115.361 U1.118@103.845,109.104
LCD_R1: RP7.3 U1.119 | length 10.9
  Top Layer w0.18: RP7.3@100.467,118.475 100.467,117.731 100.838,117.36 101.275,117.36 103.445,115.19 U1.119@103.445,109.104
LCD_R2: RP7.2 U1.120 | length 11.2
  Top Layer w0.18: RP7.2@99.667,118.475 99.667,117.769 100.584,116.852 101.272,116.852 103.045,115.08 U1.120@103.045,109.104
LCD_R3: RP7.1 U1.123 | length 10.6
  Top Layer w0.18: RP7.1@98.867,118.475 98.867,116.033 101.854,113.046 101.854,109.113 U1.123@101.845,109.104
LCD_R4: RP8.4 U1.124 | length 10.9
  Top Layer w0.18: RP8.4@97.838,118.475 97.892,118.421 97.892,116.498 101.445,112.945 U1.124@101.445,109.104
LCD_R5: RP8.3 U1.125 | length 10.9
  Top Layer w0.18: RP8.3@97.028,118.357 97.028,116.852 101.045,112.835 U1.125@101.045,109.104
LCD_R6: RP8.2 U1.126 | length 11.1
  Top Layer w0.18: RP8.2@96.215,118.37 96.215,117.155 100.645,112.725 U1.126@100.645,109.104
LCD_R7: RP8.1 U1.127 | length 11.2
  Top Layer w0.18: RP8.1@95.453,118.332 95.453,117.407 100.245,112.615 U1.127@100.245,109.104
